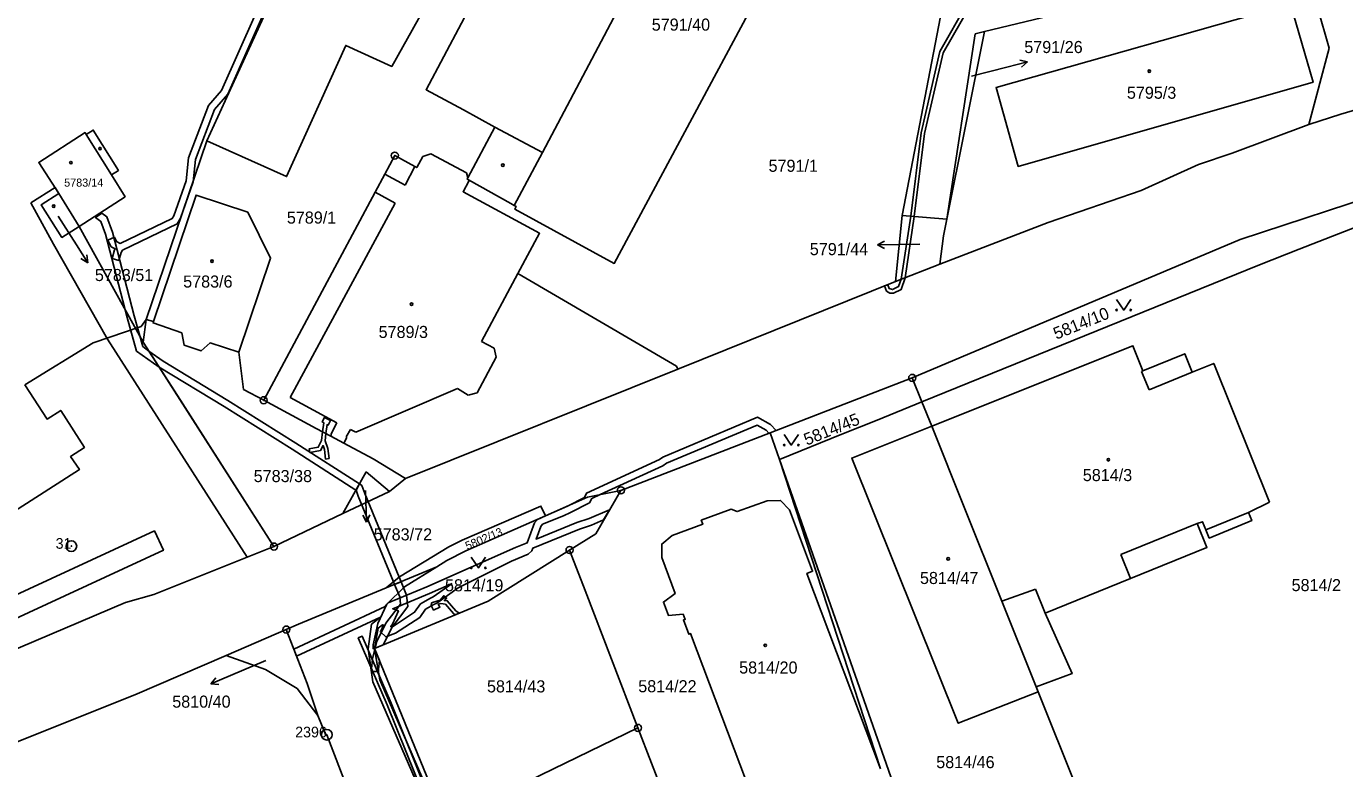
# Model space of a CAD drawing. Extents: x -644096 to -634268, y -1141430 to -1133463.
# Drawn here: x -640171 to -639985.4, y -1138819.3 to -1138714.8 of the extents above; entities that cross this region are included whole.
import ezdxf

# ---------------------------------------------------------------- set-up
doc = ezdxf.new("R2010")
doc.units = 0
for name, color, linetype in [('_CIVIL_CONSTRUCTION', 7, 'Continuous'), ('B_Hranice _3D', 7, 'Continuous'), ('M_Svah_Nasyp', 7, 'Continuous'), ('M_Svah_Zarez', 7, 'Continuous'), ('svrsek_osa_sjezdy', 7, 'Continuous'), ('svrsek_osa_VRT', 7, 'Continuous'), ('svrsek_popisy_VRT', 7, 'Continuous'), ('terminal_VRT', 7, 'Continuous')]:
    doc.layers.add(name, color=color, linetype=linetype)

msp = doc.modelspace()

# ---------------------------------------------------------------- linework, layer by layer
at = {"layer": '_CIVIL_CONSTRUCTION'}
for centre, radius in [((-640119.12, -1138733.02), 0.5), ((-640119.12, -1138733.02), 0.0303), ((-640046.26, -1138764.3), 0.5), ((-640046.26, -1138764.3), 0.0303), ((-640137.58, -1138767.44), 0.5), ((-640137.58, -1138767.44), 0.0303), ((-640087.28, -1138780.12), 0.5), ((-640087.28, -1138780.12), 0.0303), ((-640164.66, -1138787.97), 0.75), ((-640164.66, -1138787.97), 0.03), ((-640136.13, -1138788.03), 0.5), ((-640136.13, -1138788.03), 0.0303), ((-640094.51, -1138788.52), 0.5), ((-640094.51, -1138788.52), 0.0303), ((-640134.4, -1138799.71), 0.5), ((-640134.4, -1138799.71), 0.0303), ((-640128.7, -1138814.5), 0.75), ((-640084.88, -1138813.55), 0.5), ((-640084.88, -1138813.55), 0.0303), ((-640128.7, -1138814.5), 0.03)]:
    msp.add_circle(centre, radius, dxfattribs=at)
at = {"layer": 'B_Hranice _3D'}
for points in [[(-640134.12, -1138702.75), (-640143.5, -1138723.84), (-640145.37, -1138725.99), (-640148.15, -1138733.35), (-640148.52, -1138736.57), (-640150.24, -1138741.48), (-640150.46, -1138741.86), (-640157.78, -1138745.38), (-640158.31, -1138745.11), (-640158.61, -1138744.48), (-640159.51, -1138744.9), (-640159.07, -1138745.85), (-640158.51, -1138746.13), (-640158.59, -1138746.27), (-640158.92, -1138747.51), (-640157.96, -1138747.76), (-640157.67, -1138746.67), (-640157.45, -1138746.33), (-640149.75, -1138742.62), (-640149.28, -1138741.82), (-640147.53, -1138736.7), (-640147.17, -1138733.59), (-640144.49, -1138726.51), (-640142.64, -1138724.38), (-640133.18, -1138703.09)], [(-640038.56, -1138711.71), (-640042.38, -1138718.39), (-640045.01, -1138729.81), (-640046.48, -1138741.55), (-640047.8, -1138750.42), (-640047.26, -1138750.21), (-640045.98, -1138741.59), (-640044.51, -1138729.89), (-640041.9, -1138718.57), (-640038.12, -1138711.93)], [(-640113.93, -1138823.59), (-640121.25, -1138806.8), (-640121.97, -1138802.36), (-640121.48, -1138799.51), (-640120.87, -1138799.04), (-640120.69, -1138799.08), (-640121.15, -1138800.04), (-640120.39, -1138800.74), (-640119, -1138800.21), (-640115.61, -1138797.99), (-640114.82, -1138796.85), (-640113.64, -1138796.17), (-640113.22, -1138795.99), (-640110.2, -1138793.84), (-640102.69, -1138790.09), (-640100.33, -1138789.08), (-640099.83, -1138788.61), (-640099.7, -1138788.26), (-640093.13, -1138785.57), (-640091.41, -1138785.01), (-640089.71, -1138784.29), (-640088.87, -1138782.84), (-640091.77, -1138784.07), (-640093.47, -1138784.63), (-640099.23, -1138786.98), (-640098.57, -1138785.21), (-640098.3, -1138784.88), (-640095.38, -1138783.69), (-640094.36, -1138783.22), (-640091.69, -1138781.86), (-640091.39, -1138781.27), (-640090.18, -1138780.71), (-640081.36, -1138776.66), (-640080.86, -1138776.31), (-640068.1, -1138770.95), (-640066.83, -1138771.67), (-640066.45, -1138772.08), (-640066.28, -1138772.02), (-640065.44, -1138771.7), (-640066.21, -1138770.87), (-640068.04, -1138769.83), (-640081.36, -1138775.43), (-640081.86, -1138775.8), (-640092.13, -1138780.51), (-640092.43, -1138781.12), (-640094.8, -1138782.33), (-640097.91, -1138783.71), (-640099.04, -1138784.21), (-640099.45, -1138784.71), (-640100.48, -1138787.5), (-640102.13, -1138788.17), (-640114.62, -1138793.7), (-640120.05, -1138795.96), (-640120.24, -1138796.15), (-640120.47, -1138796.48), (-640133.34, -1138802.47), (-640132.97, -1138803.44), (-640121.12, -1138797.98), (-640122.42, -1138798.97), (-640122.88, -1138802.43), (-640122.23, -1138807.08), (-640114.85, -1138823.99)], [(-640198.47, -1138810.17), (-640151.7, -1138788.54), (-640152.96, -1138785.82), (-640199.64, -1138807.41)]]:
    msp.add_lwpolyline(points, dxfattribs=at)
for points in [[(-640170.35, -1138739.68), (-640167.18, -1138745.48), (-640159.57, -1138758.83), (-640139.92, -1138789.54), (-640136.13, -1138788.03), (-640154.53, -1138759.28), (-640163.58, -1138742.98), (-640166, -1138744.53), (-640168.9, -1138739.94), (-640166.43, -1138738.36), (-640166.96, -1138737.51)], [(-640154.61, -1138759.9), (-640155.83, -1138755.55), (-640158.88, -1138743.79), (-640159.67, -1138741.63), (-640160.38, -1138741.14), (-640161.25, -1138741.75), (-640160.51, -1138742.27), (-640159.84, -1138744.09), (-640156.79, -1138755.81), (-640155.47, -1138760.52), (-640152.28, -1138762.77), (-640153.74, -1138760.52)], [(-640047.8, -1138750.42), (-640048.19, -1138751.46), (-640049.04, -1138751.86), (-640049.49, -1138751.74), (-640049.71, -1138751.18), (-640050.18, -1138751.36), (-640049.89, -1138752.08), (-640049.43, -1138752.36), (-640048.92, -1138752.36), (-640047.81, -1138751.84), (-640047.26, -1138750.21)], [(-640153.74, -1138760.52), (-640152.28, -1138762.77), (-640143.13, -1138768.32), (-640133.59, -1138774.33), (-640124.6, -1138780.1), (-640124.11, -1138779.22), (-640133.05, -1138773.49), (-640142.61, -1138767.46), (-640151.74, -1138761.93)], [(-640128.37, -1138775.65), (-640128.55, -1138774.23), (-640128.93, -1138773.14), (-640128.81, -1138772.14), (-640128.65, -1138770.86), (-640128.49, -1138770.94), (-640128.16, -1138770.31), (-640129.02, -1138769.85), (-640129.34, -1138770.5), (-640129.12, -1138770.61), (-640129.28, -1138771.89), (-640129.43, -1138773.1), (-640129.9, -1138774.06), (-640131.18, -1138774.3), (-640131.09, -1138774.79), (-640129.56, -1138774.5), (-640129.23, -1138773.81), (-640129.03, -1138774.35), (-640128.86, -1138775.71)], [(-640119.31, -1138792.99), (-640118.5, -1138792.32), (-640123.36, -1138780.57), (-640123.76, -1138779.45), (-640124.11, -1138779.22), (-640124.58, -1138780.11), (-640124.3, -1138780.93)], [(-640117.29, -1138796.45), (-640117.45, -1138794.87), (-640118.24, -1138792.97), (-640119.16, -1138793.35), (-640118.43, -1138795.11), (-640118.33, -1138796.15), (-640120.36, -1138798.81), (-640121.67, -1138801.41), (-640121.88, -1138802.32), (-640120.75, -1138801.85), (-640120.73, -1138801.75), (-640119.5, -1138799.35)], [(-640111.06, -1138793.22), (-640113.72, -1138795.11), (-640114.08, -1138795.27), (-640115.52, -1138796.09), (-640116.33, -1138797.27), (-640119.46, -1138799.31), (-640119.68, -1138799.3), (-640119.43, -1138798.93), (-640118.61, -1138797.08), (-640119.4, -1138796.77), (-640114.22, -1138794.62)], [(-640119.16, -1138793.35), (-640118.24, -1138792.97), (-640118.5, -1138792.32), (-640119.31, -1138792.99)], [(-640113.95, -1138795.94), (-640113.98, -1138796.31), (-640113.65, -1138796.97), (-640112.77, -1138796.55), (-640113.01, -1138796.12), (-640112.63, -1138796.03), (-640111.99, -1138796.13), (-640110.86, -1138797.46), (-640110.61, -1138797.63), (-640110.05, -1138797.39), (-640110.52, -1138797.08), (-640111.74, -1138795.66), (-640112.13, -1138795.62), (-640111.83, -1138795.28), (-640112.22, -1138794.96), (-640112.74, -1138795.57), (-640113.22, -1138795.73)], [(-640100.2, -1138857.28), (-640090.64, -1138880.53), (-640082, -1138900.49), (-640080.17, -1138905.26), (-640079.43, -1138906.1), (-640079.21, -1138906.13), (-640079.91, -1138904.93), (-640082.53, -1138898.54), (-640088.51, -1138883.96), (-640090.1, -1138880.29), (-640099.66, -1138857), (-640114.42, -1138823.08), (-640119.63, -1138810.08), (-640123.7, -1138800.64), (-640124.26, -1138800.88), (-640120.19, -1138810.3), (-640114.96, -1138823.34)], [(-640122.41, -1138805.63), (-640121.41, -1138805.61), (-640121.42, -1138805.28), (-640121.27, -1138804.07), (-640121.92, -1138802.48), (-640122.24, -1138803.84), (-640122.42, -1138805.24)]]:
    msp.add_lwpolyline(points, close=True, dxfattribs=at)
at = {"layer": 'M_Svah_Nasyp'}
for p, q in [((-640159, -1138735.71), (-640162.56, -1138730.03)), ((-640105.03, -1138729), (-640098.3, -1138732.6)), ((-640120.52, -1138735.63), (-640117.67, -1138737.18)), ((-640117.67, -1138737.18), (-640116.29, -1138734.55)), ((-640119.06, -1138739.7), (-640133.85, -1138767.05)), ((-640121.89, -1138738.18), (-640119.06, -1138739.7)), ((-640106.92, -1138759.19), (-640101.78, -1138749.61)), ((-640105.14, -1138760.12), (-640106.92, -1138759.19)), ((-640104.86, -1138761.37), (-640105.14, -1138760.12)), ((-640107.53, -1138766.38), (-640104.86, -1138761.37)), ((-640013.96, -1138763.38), (-640013.77, -1138763.3)), ((-640013.96, -1138763.38), (-640012.92, -1138765.96)), ((-640012.92, -1138765.96), (-640006.85, -1138763.5)), ((-640124.62, -1138771.93), (-640110.29, -1138765.81)), ((-640110.29, -1138765.81), (-640108.77, -1138766.71)), ((-640133.85, -1138767.05), (-640127.28, -1138770.63)), ((-640108.77, -1138766.71), (-640107.53, -1138766.38)), ((-640127.28, -1138770.63), (-640128.15, -1138772.28)), ((-640125.96, -1138772.6), (-640125.37, -1138771.54)), ((-640125.37, -1138771.54), (-640124.62, -1138771.93)), ((-640128.15, -1138772.28), (-640128.01, -1138772.36)), ((-640128.01, -1138772.36), (-640128.11, -1138772.51)), ((-640126.3, -1138773.48), (-640125.87, -1138772.67)), ((-640125.87, -1138772.67), (-640125.96, -1138772.6)), ((-640004.91, -1138785.66), (-639998.93, -1138783.26)), ((-640016.89, -1138789.15), (-640006.14, -1138784.8)), ((-640015.51, -1138792.53), (-640016.89, -1138789.15)), ((-640033.65, -1138795.72), (-640028.92, -1138794.01)), ((-640027.53, -1138797.42), (-640028.92, -1138794.01))]:
    msp.add_line(p, q, dxfattribs=at)
at = {"layer": 'M_Svah_Zarez'}
for centre in [(-640012.88, -1138721.14), (-640160.62, -1138732.03), (-640164.73, -1138734.02), (-640103.91, -1138734.37), (-640167.15, -1138740.13), (-640144.86, -1138747.87), (-640116.76, -1138753.92), (-640018.64, -1138775.82), (-640041.2, -1138789.76), (-640066.96, -1138801.93)]:
    msp.add_circle(centre, 0.175, dxfattribs=at)
at = {"layer": 'svrsek_osa_sjezdy'}
for points in [[(-640017.48, -1138753.25), (-640016.48, -1138754.75), (-640015.48, -1138753.25)], [(-640064.29, -1138772.26), (-640063.29, -1138773.76), (-640062.29, -1138772.26)], [(-640108.35, -1138789.54), (-640107.35, -1138791.04), (-640106.35, -1138789.54)]]:
    msp.add_lwpolyline(points, dxfattribs=at)
for centre in [(-640017.48, -1138754.75), (-640015.48, -1138754.75), (-640064.29, -1138773.76), (-640062.29, -1138773.76), (-640108.35, -1138791.04), (-640106.35, -1138791.04)]:
    msp.add_circle(centre, 0.1, dxfattribs=at)
at = {"layer": 'svrsek_popisy_VRT'}
for p, q in [((-640030.02, -1138719.83), (-640031.11, -1138719.59)), ((-640037.91, -1138721.84), (-640032.93, -1138720.56)), ((-640032.93, -1138720.56), (-640030.02, -1138719.83)), ((-640030.02, -1138719.83), (-640030.87, -1138720.56)), ((-640166.5, -1138741.54), (-640163.95, -1138745.56)), ((-640163.95, -1138745.56), (-640162.36, -1138748.1)), ((-640051.17, -1138745.59), (-640050.18, -1138745.07)), ((-640048.17, -1138745.54), (-640051.17, -1138745.59)), ((-640051.17, -1138745.59), (-640050.16, -1138746.08)), ((-640045.21, -1138745.46), (-640048.17, -1138745.54)), ((-640162.36, -1138748.1), (-640162.47, -1138746.99)), ((-640162.36, -1138748.1), (-640163.32, -1138747.52)), ((-640123.25, -1138780.16), (-640123.2, -1138781.59)), ((-640123.2, -1138781.59), (-640123.09, -1138784.59)), ((-640123.09, -1138784.59), (-640123.63, -1138783.61)), ((-640123.09, -1138784.59), (-640122.63, -1138783.57)), ((-640137.26, -1138804.04), (-640142.26, -1138806.19)), ((-640142.26, -1138806.19), (-640145.02, -1138807.36)), ((-640145.02, -1138807.36), (-640144.3, -1138806.51)), ((-640145.02, -1138807.36), (-640143.91, -1138807.43))]:
    msp.add_line(p, q, dxfattribs=at)
at = {"layer": 'terminal_VRT'}
for p, q in [((-640145.57, -1138730.94), (-640117.27, -1138669.06)), ((-640018.68, -1138711.37), (-640036.08, -1138715.57)), ((-640036.08, -1138715.57), (-640041.4, -1138741.94)), ((-640037.42, -1138715.89), (-640041.4, -1138741.94)), ((-640036.08, -1138715.57), (-640037.42, -1138715.89)), ((-640154.14, -1138756.1), (-640145.57, -1138730.94)), ((-640166.43, -1138738.36), (-640163.58, -1138742.98)), ((-640048.6, -1138750.73), (-640047.69, -1138741.46)), ((-640047.69, -1138741.46), (-640041.4, -1138741.94)), ((-640042.38, -1138748.29), (-640048.6, -1138750.73)), ((-640048.6, -1138750.73), (-640079.25, -1138763.05)), ((-640153.09, -1138756.37), (-640154.14, -1138756.1)), ((-640079.25, -1138763.05), (-640117.63, -1138778.47)), ((-640066.28, -1138772.02), (-640046.26, -1138764.3)), ((-640046.26, -1138764.3), (-640044.9, -1138767.67)), ((-640044.9, -1138767.67), (-640043.52, -1138771.11)), ((-640087.28, -1138780.12), (-640066.28, -1138772.02)), ((-640064.94, -1138775.78), (-640066.28, -1138772.02)), ((-640064.94, -1138775.78), (-640056.17, -1138772.23)), ((-640064.94, -1138775.78), (-640050.74, -1138819.32)), ((-640048.32, -1138823.09), (-640064.94, -1138775.78)), ((-640126.44, -1138783.4), (-640123.17, -1138777.53)), ((-640123.17, -1138777.53), (-640119.88, -1138780.27)), ((-640119.88, -1138780.27), (-640117.63, -1138778.47)), ((-640119.88, -1138780.27), (-640126.44, -1138783.4)), ((-640136.13, -1138788.03), (-640126.44, -1138783.4)), ((-640113.2, -1138790.88), (-640120.34, -1138793.84)), ((-640142.85, -1138803.35), (-640134.4, -1138799.71)), ((-640112.01, -1138826.66), (-640121.97, -1138802.36)), ((-640155.74, -1138808.9), (-640142.85, -1138803.35)), ((-640028.81, -1138807.75), (-640028.52, -1138808.47)), ((-640174.17, -1138816.28), (-640155.74, -1138808.9)), ((-640084.88, -1138813.55), (-640112.01, -1138826.66)), ((-640084.88, -1138813.55), (-640076.92, -1138834.23))]:
    msp.add_line(p, q, dxfattribs=at)
for points in [[(-640145.57, -1138730.94), (-640134.36, -1138735.97), (-640126.03, -1138717.51), (-640119.54, -1138720.47), (-640099.85, -1138685.31), (-640108.02, -1138681.63), (-640109.34, -1138681.04), (-640106.12, -1138674.13), (-640106.87, -1138673.79)], [(-640108.83, -1138736.17), (-640105.03, -1138729), (-640109.46, -1138726.58), (-640114.72, -1138723.76), (-640094.81, -1138686.21), (-640097, -1138685.02), (-640093.59, -1138678.08), (-640091.23, -1138679.35), (-640089.03, -1138675.33), (-640072.64, -1138683.97)], [(-640047.69, -1138741.46), (-640042.29, -1138713.43), (-640040.54, -1138712.16), (-640037.98, -1138708.51), (-640029.44, -1138699.06), (-640071.54, -1138682.13)], [(-640102.3, -1138740.04), (-640098.3, -1138732.6), (-640072.64, -1138683.97)], [(-640072.64, -1138683.97), (-640058.06, -1138691.97), (-640088.21, -1138748.18), (-640102.23, -1138740.55), (-640102.03, -1138740.19), (-640102.3, -1138740.04)], [(-639990.4, -1138728.62), (-639987.55, -1138717.88), (-639990.85, -1138706.4), (-639983.25, -1138704.38)], [(-639992.99, -1138711.7), (-639989.81, -1138722.7), (-640031.34, -1138734.53), (-640034.45, -1138723.45), (-639992.99, -1138711.7)], [(-639990.4, -1138728.62), (-639985.92, -1138727.18), (-639978.08, -1138724.87)], [(-640042.38, -1138748.29), (-640027.11, -1138742.44), (-640014, -1138737.93), (-640005.94, -1138734.27), (-640001.23, -1138732.66), (-639990.4, -1138728.62)], [(-640166.43, -1138738.36), (-640169.25, -1138733.98), (-640162.74, -1138729.77), (-640162.56, -1138730.03), (-640161.57, -1138729.43), (-640158.04, -1138735.11), (-640159, -1138735.71), (-640157.1, -1138738.82), (-640163.58, -1138742.98)], [(-640137.58, -1138767.44), (-640121.89, -1138738.18), (-640120.52, -1138735.63), (-640119.12, -1138733.02), (-640116.29, -1138734.55), (-640116.02, -1138734.71), (-640115.17, -1138733.16), (-640114.03, -1138732.77), (-640109.04, -1138735.46), (-640108.83, -1138736.17)], [(-640108.83, -1138736.17), (-640108.92, -1138736.34), (-640108.75, -1138736.43)], [(-640079.25, -1138763.05), (-640079.45, -1138762.66), (-640101.78, -1138749.61), (-640098.74, -1138743.94), (-640109.5, -1138738.1), (-640108.7, -1138736.61), (-640108.75, -1138736.43)], [(-640108.75, -1138736.43), (-640102.78, -1138739.78), (-640102.3, -1138740.04)], [(-640046.26, -1138764.3), (-640000.08, -1138744.84), (-639978.65, -1138737.8)], [(-640163.58, -1138742.98), (-640166, -1138744.53), (-640168.9, -1138739.94), (-640166.43, -1138738.36)], [(-640141.06, -1138760.67), (-640136.62, -1138747.45), (-640139.83, -1138740.98), (-640147.09, -1138738.57), (-640153.09, -1138756.37)], [(-639977.69, -1138740.62), (-639979.87, -1138741.53), (-639991.78, -1138746.19), (-639997.34, -1138748.41), (-640044.9, -1138767.67)], [(-640041.4, -1138741.94), (-640041.86, -1138744.29), (-640042.38, -1138748.29)], [(-640171.21, -1138765.27), (-640161.58, -1138759.38), (-640154.85, -1138757.05), (-640154.14, -1138756.1)], [(-640154.14, -1138756.1), (-640154.53, -1138759.28), (-640149.31, -1138767.43), (-640136.13, -1138788.03)], [(-640141.06, -1138760.67), (-640145.12, -1138759.35), (-640146.4, -1138760.5), (-640148.79, -1138759.67), (-640149.13, -1138757.97), (-640153.15, -1138756.56), (-640153.09, -1138756.37)], [(-640043.52, -1138771.11), (-640015.18, -1138759.77), (-640013.77, -1138763.3), (-640007.88, -1138760.91), (-640006.85, -1138763.5), (-640003.8, -1138762.27), (-639995.96, -1138781.8)], [(-640137.58, -1138767.44), (-640140.44, -1138765.91), (-640141.06, -1138760.67)], [(-640213.15, -1138807.88), (-640212.74, -1138808.5), (-640194.54, -1138796.95), (-640192.68, -1138799.87), (-640189, -1138797.47), (-640190.79, -1138794.62), (-640163.52, -1138777.21), (-640164.77, -1138775.36), (-640162.82, -1138774.09), (-640166.16, -1138768.88), (-640168.09, -1138770.09), (-640171.21, -1138765.27)], [(-640117.63, -1138778.47), (-640122.15, -1138775.7), (-640126.3, -1138773.48), (-640128.11, -1138772.51), (-640130.2, -1138771.4), (-640137.58, -1138767.44)], [(-640056.17, -1138772.23), (-640051.22, -1138770.23), (-640044.9, -1138767.67)], [(-640028.52, -1138808.47), (-640039.77, -1138812.9), (-640054.77, -1138775.59), (-640049.83, -1138773.62), (-640043.52, -1138771.11)], [(-640043.52, -1138771.11), (-640038.95, -1138782.49), (-640033.65, -1138795.72), (-640028.81, -1138807.75)], [(-640097.91, -1138783.71), (-640091.97, -1138781.08), (-640087.28, -1138780.12)], [(-640087.28, -1138780.12), (-640090.83, -1138786.22), (-640094.51, -1138788.52)], [(-640120.34, -1138793.84), (-640118.45, -1138792.28), (-640111.5, -1138788.08), (-640109.62, -1138787.14), (-640098.55, -1138782.34), (-640097.91, -1138783.71)], [(-640067.87, -1138825.75), (-640077.46, -1138800.28), (-640077.71, -1138800.37), (-640078.47, -1138798.36), (-640078.22, -1138798.27), (-640078.53, -1138797.52), (-640080.59, -1138797.71), (-640081.29, -1138795.84), (-640079.62, -1138794.62), (-640081.54, -1138789.55), (-640081.52, -1138787.67), (-640080.07, -1138786.48), (-640075.76, -1138784.9), (-640075.97, -1138784.33), (-640071.76, -1138782.77), (-640070.91, -1138783.12), (-640066.7, -1138781.58), (-640064.8, -1138781.53), (-640063.56, -1138782.86), (-640060.3, -1138791.51), (-640061.09, -1138791.8), (-640050.74, -1138819.32)], [(-639995.96, -1138781.8), (-639998.93, -1138783.26), (-639998.46, -1138784.38), (-640004.43, -1138786.84), (-640004.91, -1138785.66), (-640005.37, -1138784.55), (-640006.14, -1138784.8), (-640004.77, -1138788.16), (-640015.51, -1138792.53), (-640027.53, -1138797.42), (-640023.76, -1138805.9), (-640028.81, -1138807.75)], [(-640097.91, -1138783.71), (-640109.12, -1138788.63), (-640111.77, -1138790), (-640113.2, -1138790.88)], [(-640136.13, -1138788.03), (-640153.07, -1138794.78), (-640157.02, -1138795.88), (-640174.04, -1138803.13), (-640199.31, -1138813.99), (-640220.4, -1138828.54)], [(-640121.97, -1138802.36), (-640105.99, -1138795.7), (-640094.51, -1138788.52)], [(-640094.51, -1138788.52), (-640092.31, -1138794.23), (-640084.88, -1138813.55)], [(-640121.97, -1138802.36), (-640122.16, -1138802.44), (-640122.15, -1138801.85), (-640121.53, -1138798.84), (-640120.24, -1138796.15), (-640117.75, -1138793.68), (-640113.2, -1138790.88)], [(-640134.4, -1138799.71), (-640132.69, -1138798.97), (-640120.34, -1138793.84)], [(-640134.4, -1138799.71), (-640131.48, -1138807.3), (-640129.96, -1138811.81)], [(-640129.96, -1138811.81), (-640132.87, -1138807.99), (-640137.31, -1138805.34), (-640142.85, -1138803.35)], [(-640028.52, -1138808.47), (-640017.63, -1138835.64), (-640018.7, -1138836.13), (-640010.06, -1138854.71)], [(-640124.62, -1138825.15), (-640128.7, -1138814.54), (-640128.81, -1138814.58), (-640129.96, -1138811.81)]]:
    msp.add_lwpolyline(points, dxfattribs=at)

# ---------------------------------------------------------------- texts
at = {"layer": '_CIVIL_CONSTRUCTION'}
for s, p in [('31', (-640166.88, -1138788.34)), ('2396', (-640133.15, -1138814.88))]:
    msp.add_text(s, height=1.5, dxfattribs=at).set_placement(p)
at = {"layer": 'svrsek_osa_VRT'}
for s, height, p in [('5791/40', 1.7, (-640082.94, -1138715.44)), ('5791/26', 1.7, (-640030.48, -1138718.59)), ('5795/3', 1.7, (-640016.03, -1138725.02)), ('5791/1', 1.7, (-640066.49, -1138735.3)), ('5783/14', 1.14, (-640165.68, -1138737.39)), ('5789/1', 1.7, (-640134.32, -1138742.59)), ('5791/44', 1.7, (-640060.68, -1138747.03)), ('5783/51', 1.7, (-640161.35, -1138750.67)), ('5783/6', 1.7, (-640148.92, -1138751.59)), ('5789/3', 1.7, (-640121.4, -1138758.68)), ('5814/3', 1.7, (-640022.24, -1138778.82)), ('5783/38', 1.7, (-640138.99, -1138778.96)), ('5783/72', 1.7, (-640122.09, -1138787.16)), ('5814/47', 1.7, (-640045.17, -1138793.3)), ('5814/19', 1.7, (-640112.05, -1138794.33)), ('5814/2', 1.7, (-639992.84, -1138794.3)), ('5814/20', 1.7, (-640070.63, -1138805.9)), ('5814/43', 1.7, (-640106.14, -1138808.55)), ('5814/22', 1.7, (-640084.84, -1138808.53)), ('5810/40', 1.7, (-640150.46, -1138810.7)), ('5814/46', 1.7, (-640042.88, -1138819.21))]:
    msp.add_text(s, height=height, dxfattribs=at).set_placement(p)
for s, height, rotation, p in [('5814/10', 1.7, 22, (-640025.97, -1138758.93)), ('5814/45', 1.7, 22, (-640061.11, -1138773.84)), ('5802/13', 1.14, 23, (-640108.9, -1138788.52))]:
    msp.add_text(s, height=height, rotation=rotation, dxfattribs=at).set_placement(p)

doc.saveas('drawing.dxf')
